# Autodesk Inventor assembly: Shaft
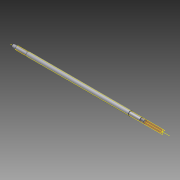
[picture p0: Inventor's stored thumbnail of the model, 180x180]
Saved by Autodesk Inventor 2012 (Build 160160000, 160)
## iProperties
Created: 2007-07
Part Number: Shaft
Document SubType Name: Assembly
Designer: Ed O'Halloran
ClientObjectVersion: 1
Author: Ed O'Halloran
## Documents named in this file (2)
- C:\CMU\Datasets\Session 6\Cluster Ex 1\Workspaces\Workspace\Drive Shaft Assembly\Design Accelerator\Shaft1.iam
- C:\CMU\Datasets\Session 6\Cluster Ex 1\Workspaces\Workspace\Drive Shaft Assembly\Design Accelerator\Shaft1.ipt
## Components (1 placed, 1 different names)
1. Shaft:1
